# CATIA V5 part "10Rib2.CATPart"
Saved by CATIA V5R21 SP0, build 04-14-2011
Part number: Rib1_tip
Bounding box of the stored display mesh (mm): x 0 to 6.5, y -3.709 to 3.709, z -223.75 to 3.75
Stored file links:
  K:\Arm_Detailed_Design_Assembly_Manu\10Rib2.CATPart
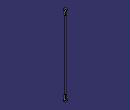
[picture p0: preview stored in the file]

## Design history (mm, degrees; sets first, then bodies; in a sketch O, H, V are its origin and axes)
Body1 (main body)
  Sketch1 on yz-plane, origin (0, 0, 0), H (0, 1, 0), V (0, 0, 1)
    arc A1 centre (0, 0) radius 3.75 from (2, -3.1721) to (-2, -3.1721) ccw
    point P1 (-2, -3.1721)
    line L1 (-2, -3.1721) -> (-2, -14)
    point P2 (-2, -14)
    line L2 (-2, -14) -> (0, -14)
    point P3 (0, -14)
    point P4 (2, -14)
    point P5 (2, -3.1721)
    line L3 (2, -3.1721) -> (2, -14)
    point P6 (0, -14)
    line L4 (2, -14) -> (0, -14)
    axis line L5 (-144.6893, -110) -> (122.6008, -110)
    construction line L6 through (0, -220) direction (0, -1)
    point P10 (-2, -216.8279)
    point P11 (-2, -206)
    point P12 (0, -206)
    point P13 (2, -206)
    point P14 (2, -216.8279)
    point P15 (0, -206)
    arc A2 centre (0, -220) radius 3.75 from (2, -216.8279) to (-2, -216.8279) cw
    line L7 (-2, -216.8279) -> (-2, -206)
    line L8 (-2, -206) -> (0, -206)
    line L9 (2, -216.8279) -> (2, -206)
    line L10 (2, -206) -> (0, -206)
    radius A1 = 3.75
    distance H L4 = 14
    distance L1 L3 = 4
    distance L5 H = 110
    vertical: L1 V
    coincidence: P3 V, P3 P6
    horizontal: L2 H, L5 H
    symmetry: P2 P4 V, P1 P5 V, L1 L3 V, P3 P6 V, L2 L4 V, V L6 L5, P1 P10 L5, P2 P11 L5, P3 P12 L5, P4 P13 L5, P5 P14 L5, P6 P15 L5, A1 A2 L5, L1 L7 L5, L2 L8 L5, L3 L9 L5, L4 L10 L5
  Pad1: profile Sketch1, direction (1, 0, 0), length 3.5
  Sketch2 on end face of Pad1, origin (3.5, 0, 0), H (0, 1, 0), V (0, 0, 1)
    circle A1 centre (0, 0) radius 1.25
    radius A1 = 1.25
  Sketch3 on face of Pad1 from Sketch1.L2, origin (0, 0, -14), H (1, 0, 0), V (0, -1, 0)
    circle A1 centre (1.75, 0) radius 1
    point P1 (1.75, 0)
    radius A1 = 1
    distance P1 V = 1.75
    coincidence: P1 H
  Pocket1: profile Sketch3, direction (0, 0, 1), length 5
  Pad2: profile Sketch2, direction (1, 0, 0), length 3
  Sketch4 on face of Pad1 from Sketch1.L10, origin (0, 0, -206), H (1, 0, 0), V (0, 1, 0)
    circle A1 centre (1.75, 0) radius 1
    point P1 (1.75, 0)
    radius A1 = 1
    distance P1 V = 1.75
    coincidence: P1 H
  Pocket2: profile Sketch4, direction (0, 0, -1), length 5
  Sketch5 on end face of Pocket2, origin (0, 0, -211), H (1, 0, 0), V (0, 1, 0)
    circle A1 centre (1.75, 0) radius 1
    point P1 (1.75, 0)
    radius A1 = 1
    distance P1 V = 1.75
    coincidence: P1 H
  Pad3: profile Sketch5, direction (0, 0, 1), up to end face of Pocket1
  Sketch6 on end face of Pad1, origin (3.5, 0, 0), H (0, 1, 0), V (0, 0, 1)
    circle A1 centre (0, -220) radius 1.25
    point P1 (0, -220)
    reference projected arc E1 centre (0, -220) radius 3.75 from (-1.875, -216.7524) to (1.875, -216.7524) ccw from edge [face of Pad1 from Sketch1.A2 | end face of Pad1]
    radius A1 = 1.25
    coincidence: P1 V
    concentricity: A1 E1
  Pad4: profile Sketch6, direction (1, 0, 0), length 3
